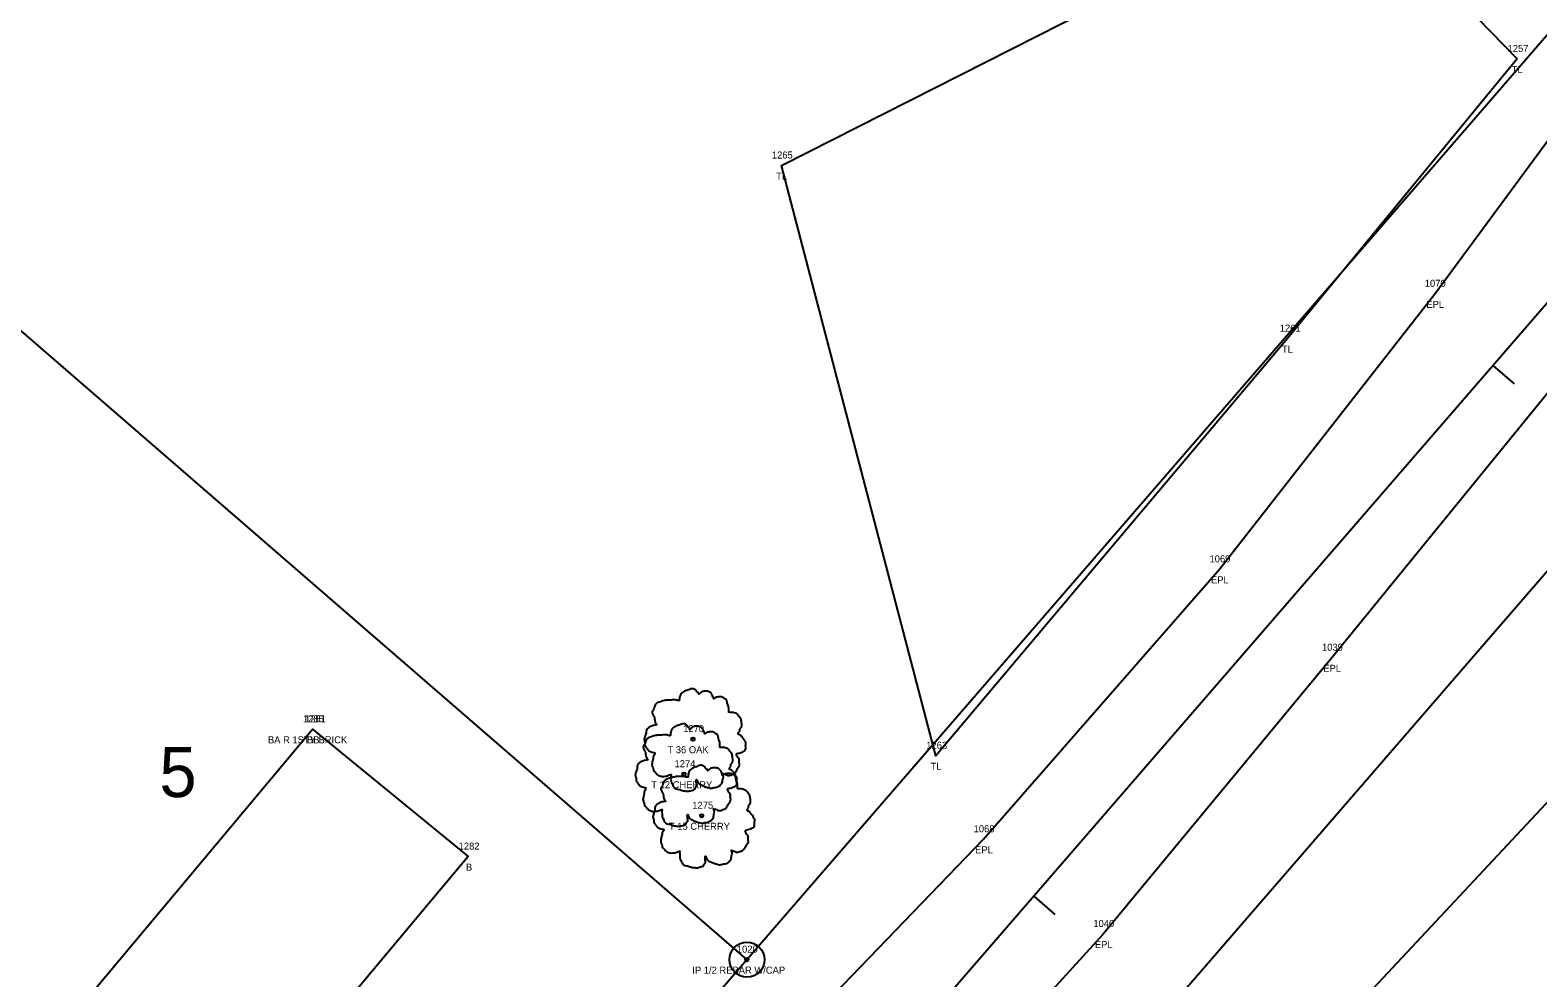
# Model space of a CAD drawing. Extents: x 1812113 to 1819860, y 1177290 to 1181185.
# Drawn here: x 1813774.2 to 1813989, y 1178275.6 to 1178410.7 of the extents above; entities that cross this region are included whole.
import ezdxf

# ---------------------------------------------------------------- set-up
doc = ezdxf.new("R2010")
doc.units = 0
for name, color, linetype in [('RD_EX_Bldg', 7, 'Continuous'), ('RD_EX_Bldg_txCode', 7, 'Continuous'), ('RD_EX_DV_Prop', 7, 'Continuous'), ('RD_EX_DV_Prop_txCode', 7, 'Continuous'), ('RD_EX_DV_PropPin', 7, 'Continuous'), ('RD_EX_DV_TX_Prop', 7, 'Continuous'), ('RD_EX_Fence_Other', 7, 'Continuous'), ('RD_EX_Road', 7, 'Continuous'), ('RD_EX_Road_txCode', 7, 'Continuous'), ('RD_EX_VEG', 7, 'Continuous'), ('RD_EX_VEG_txCode', 7, 'Continuous'), ('RD_HC_CL', 7, 'Continuous'), ('RD_HC_Data_Tic', 7, 'Continuous'), ('RD_SMD_Locator', 7, 'Continuous')]:
    doc.layers.add(name, color=color, linetype=linetype)

msp = doc.modelspace()

# ---------------------------------------------------------------- linework, layer by layer
at = {"layer": 'RD_EX_Bldg'}
msp.add_lwpolyline([(1813814.41, 1178311.05), (1813836.59, 1178292.91), (1813805.22, 1178255.39), (1813783.05, 1178273.53), (1813814.41, 1178311.05)], dxfattribs=at)
at = {"layer": 'RD_EX_DV_Prop'}
for p, q in [((1813876.31, 1178278.23), (1814007.16, 1178429.49)), ((1813914.12, 1178245.52), (1814044.97, 1178396.77)), ((1813876.31, 1178278.23), (1813762.97, 1178376.42)), ((1813820.68, 1178213.93), (1813876.31, 1178278.23))]:
    msp.add_line(p, q, dxfattribs=at)
at = {"layer": 'RD_EX_DV_PropPin'}
for radius in [2.5, 0.25]:
    msp.add_circle((1813876.31, 1178278.23), radius, dxfattribs=at)
at = {"layer": 'RD_EX_Fence_Other'}
msp.add_lwpolyline([(1814039.17, 1178321.6), (1814032.91, 1178334.96), (1814018.04, 1178330.3), (1813949.86, 1178257.34), (1813966.14, 1178241)], dxfattribs=at)
at = {"layer": 'RD_EX_Road'}
for p, q in [((1813974.31, 1178373.09), (1814001.91, 1178410.56)), ((1813943.63, 1178333.84), (1813974.31, 1178373.09)), ((1813991.69, 1178360.57), (1813959.64, 1178321.24)), ((1813910.02, 1178295.38), (1813943.63, 1178333.84)), ((1813959.64, 1178321.24), (1813927.09, 1178281.88)), ((1813874.69, 1178258.74), (1813910.02, 1178295.38)), ((1813927.09, 1178281.88), (1813899.48, 1178251.69))]:
    msp.add_line(p, q, dxfattribs=at)
at = {"layer": 'RD_EX_VEG'}
msp.add_lwpolyline([(1813961.33, 1178431.97), (1813986.04, 1178406.55), (1813953.31, 1178366.71), (1813903.24, 1178307.28), (1813881.24, 1178391.37), (1813961.33, 1178431.97)], dxfattribs=at)
for centre, radius in [((1813868.62, 1178309.64), 0.25), ((1813868.61, 1178309.62), 0.0001), ((1813867.35, 1178304.65), 0.25), ((1813867.34, 1178304.63), 0.0001), ((1813869.87, 1178298.73), 0.25), ((1813869.86, 1178298.71), 0.0001)]:
    msp.add_circle(centre, radius, dxfattribs=at)
for points in [[(1813868.75, 1178316.81), (1813868.45, 1178316.83), (1813868.13, 1178316.73), (1813867.88, 1178316.63), (1813867.65, 1178316.56), (1813867.43, 1178316.46), (1813867.13, 1178316.28), (1813866.9, 1178316.08), (1813866.78, 1178315.83), (1813866.73, 1178315.61), (1813866.68, 1178315.33), (1813866.68, 1178315.16), (1813866.55, 1178315.13), (1813866.4, 1178315.16), (1813866.15, 1178315.23), (1813865.9, 1178315.23), (1813865.65, 1178315.23), (1813865.3, 1178315.21), (1813864.95, 1178315.21), (1813864.68, 1178315.16), (1813864.35, 1178315.11), (1813863.98, 1178314.98), (1813863.63, 1178314.86), (1813863.33, 1178314.61), (1813863.08, 1178314.13), (1813862.96, 1178313.78), (1813862.81, 1178313.53), (1813862.96, 1178313.08), (1813863.13, 1178312.73), (1813863.15, 1178312.53), (1813863.23, 1178312.11), (1813863.33, 1178311.88), (1813863.45, 1178311.68), (1813863.38, 1178311.66), (1813863.01, 1178311.61), (1813862.71, 1178311.51), (1813862.28, 1178311.28), (1813862.06, 1178311.06), (1813861.96, 1178310.73), (1813861.93, 1178310.38), (1813861.83, 1178310.18), (1813861.76, 1178309.91), (1813861.73, 1178309.83), (1813861.68, 1178309.51), (1813861.78, 1178309.06), (1813861.81, 1178308.71), (1813861.93, 1178308.49), (1813862.08, 1178308.31), (1813862.26, 1178308.06), (1813862.66, 1178307.84), (1813862.98, 1178307.74), (1813863.18, 1178307.71), (1813863.01, 1178307.21), (1813862.96, 1178306.86), (1813862.83, 1178306.46), (1813862.83, 1178306.39), (1813862.78, 1178305.91), (1813862.93, 1178305.59), (1813863.01, 1178305.21), (1813863.18, 1178304.99), (1813863.45, 1178304.69), (1813863.78, 1178304.46), (1813864.28, 1178304.34), (1813864.68, 1178304.36), (1813865.25, 1178304.54), (1813865.5, 1178304.61), (1813865.48, 1178304.44), (1813865.5, 1178304.06), (1813865.5, 1178303.64), (1813865.65, 1178303.31), (1813865.75, 1178303.04), (1813865.9, 1178302.79), (1813866.23, 1178302.56), (1813866.63, 1178302.49), (1813867.05, 1178302.34), (1813867.5, 1178302.26), (1813868, 1178302.24), (1813868.6, 1178302.39), (1813868.88, 1178302.51), (1813868.98, 1178302.69), (1813869.18, 1178303.06), (1813869.13, 1178303.29), (1813869.15, 1178303.89), (1813869.25, 1178303.71), (1813869.43, 1178303.36), (1813869.93, 1178303.06), (1813870.33, 1178302.89), (1813870.8, 1178302.74), (1813871.1, 1178302.66), (1813871.58, 1178302.74), (1813871.95, 1178302.81), (1813872.33, 1178302.94), (1813872.63, 1178303.21), (1813872.8, 1178303.49), (1813872.85, 1178303.76), (1813872.93, 1178304.14), (1813872.98, 1178304.31)], [(1813872.98, 1178304.31), (1813872.9, 1178304.49), (1813872.85, 1178304.74), (1813872.93, 1178304.71), (1813873.1, 1178304.66), (1813873.38, 1178304.54), (1813873.6, 1178304.46), (1813873.93, 1178304.49), (1813874.2, 1178304.59), (1813874.65, 1178304.86), (1813874.92, 1178305.34), (1813875.2, 1178305.74), (1813875.27, 1178306.06), (1813875.22, 1178306.29), (1813875.2, 1178306.79), (1813875, 1178307.04), (1813874.95, 1178307.16), (1813874.85, 1178307.56), (1813874.92, 1178307.61), (1813875.2, 1178307.66), (1813875.57, 1178307.79), (1813875.85, 1178307.91), (1813876.07, 1178308.09), (1813876.15, 1178308.31), (1813876.12, 1178308.71), (1813876.17, 1178309.11), (1813876.1, 1178309.26), (1813876, 1178309.41), (1813875.92, 1178309.61), (1813875.77, 1178309.76), (1813875.67, 1178309.91), (1813875.57, 1178310.01), (1813875.45, 1178310.16), (1813875.27, 1178310.28), (1813875.12, 1178310.33), (1813875.07, 1178310.48), (1813875.22, 1178310.68), (1813875.27, 1178310.78), (1813875.3, 1178311.01), (1813875.52, 1178311.36), (1813875.57, 1178311.76), (1813875.52, 1178312.18), (1813875.47, 1178312.46), (1813875.32, 1178312.73), (1813875.12, 1178312.98), (1813875, 1178313.16), (1813874.82, 1178313.28), (1813874.5, 1178313.41), (1813874.25, 1178313.46), (1813873.9, 1178313.46), (1813873.7, 1178313.51), (1813873.73, 1178313.56), (1813873.73, 1178313.71), (1813873.73, 1178313.98), (1813873.65, 1178314.43), (1813873.5, 1178314.93), (1813873.5, 1178314.96), (1813873.4, 1178315.21), (1813873.18, 1178315.41), (1813873, 1178315.51), (1813872.8, 1178315.63), (1813872.55, 1178315.66), (1813872.25, 1178315.66), (1813871.98, 1178315.61), (1813871.78, 1178315.51), (1813871.6, 1178315.38), (1813871.53, 1178315.53), (1813871.43, 1178315.83), (1813871.38, 1178315.98), (1813871.23, 1178316.16), (1813871, 1178316.36), (1813870.55, 1178316.48), (1813869.93, 1178316.41), (1813869.63, 1178316.21), (1813869.48, 1178316.03), (1813869.43, 1178316.16), (1813869.23, 1178316.36), (1813869.13, 1178316.53), (1813868.95, 1178316.66), (1813868.8, 1178316.76), (1813868.7, 1178316.81)], [(1813867.48, 1178311.82), (1813867.18, 1178311.84), (1813866.86, 1178311.74), (1813866.61, 1178311.64), (1813866.38, 1178311.57), (1813866.16, 1178311.47), (1813865.86, 1178311.29), (1813865.63, 1178311.09), (1813865.51, 1178310.84), (1813865.46, 1178310.62), (1813865.41, 1178310.34), (1813865.41, 1178310.17), (1813865.28, 1178310.14), (1813865.13, 1178310.17), (1813864.88, 1178310.24), (1813864.63, 1178310.24), (1813864.38, 1178310.24), (1813864.03, 1178310.22), (1813863.68, 1178310.22), (1813863.41, 1178310.17), (1813863.08, 1178310.12), (1813862.71, 1178309.99), (1813862.36, 1178309.87), (1813862.06, 1178309.62), (1813861.81, 1178309.14), (1813861.68, 1178308.79), (1813861.53, 1178308.54), (1813861.68, 1178308.09), (1813861.86, 1178307.74), (1813861.88, 1178307.54), (1813861.96, 1178307.12), (1813862.06, 1178306.89), (1813862.18, 1178306.69), (1813862.11, 1178306.67), (1813861.73, 1178306.62), (1813861.43, 1178306.52), (1813861.01, 1178306.29), (1813860.78, 1178306.07), (1813860.68, 1178305.74), (1813860.66, 1178305.39), (1813860.56, 1178305.19), (1813860.48, 1178304.92), (1813860.46, 1178304.84), (1813860.41, 1178304.52), (1813860.51, 1178304.07), (1813860.53, 1178303.72), (1813860.66, 1178303.5), (1813860.81, 1178303.32), (1813860.98, 1178303.07), (1813861.38, 1178302.85), (1813861.71, 1178302.75), (1813861.91, 1178302.72), (1813861.73, 1178302.22), (1813861.68, 1178301.87), (1813861.56, 1178301.47), (1813861.56, 1178301.4), (1813861.51, 1178300.92), (1813861.66, 1178300.6), (1813861.73, 1178300.22), (1813861.91, 1178300), (1813862.18, 1178299.7), (1813862.51, 1178299.47), (1813863.01, 1178299.35), (1813863.41, 1178299.37), (1813863.98, 1178299.55), (1813864.23, 1178299.62), (1813864.21, 1178299.45), (1813864.23, 1178299.07), (1813864.23, 1178298.65), (1813864.38, 1178298.32), (1813864.48, 1178298.05), (1813864.63, 1178297.8), (1813864.96, 1178297.57), (1813865.36, 1178297.5), (1813865.78, 1178297.35), (1813866.23, 1178297.27), (1813866.73, 1178297.25), (1813867.33, 1178297.4), (1813867.61, 1178297.52), (1813867.71, 1178297.7), (1813867.91, 1178298.07), (1813867.86, 1178298.3), (1813867.88, 1178298.9), (1813867.98, 1178298.72), (1813868.15, 1178298.37), (1813868.65, 1178298.07), (1813869.05, 1178297.9), (1813869.53, 1178297.75), (1813869.83, 1178297.67), (1813870.3, 1178297.75), (1813870.68, 1178297.82), (1813871.05, 1178297.95), (1813871.35, 1178298.22), (1813871.53, 1178298.5), (1813871.58, 1178298.77), (1813871.65, 1178299.15), (1813871.7, 1178299.32)], [(1813871.7, 1178299.32), (1813871.63, 1178299.5), (1813871.58, 1178299.75), (1813871.65, 1178299.72), (1813871.83, 1178299.67), (1813872.1, 1178299.55), (1813872.33, 1178299.47), (1813872.65, 1178299.5), (1813872.93, 1178299.6), (1813873.38, 1178299.87), (1813873.65, 1178300.35), (1813873.93, 1178300.75), (1813874, 1178301.07), (1813873.95, 1178301.3), (1813873.93, 1178301.8), (1813873.73, 1178302.05), (1813873.68, 1178302.17), (1813873.58, 1178302.57), (1813873.65, 1178302.62), (1813873.93, 1178302.67), (1813874.3, 1178302.8), (1813874.58, 1178302.92), (1813874.8, 1178303.1), (1813874.88, 1178303.32), (1813874.85, 1178303.72), (1813874.9, 1178304.12), (1813874.83, 1178304.27), (1813874.73, 1178304.42), (1813874.65, 1178304.62), (1813874.5, 1178304.77), (1813874.4, 1178304.92), (1813874.3, 1178305.02), (1813874.18, 1178305.17), (1813874, 1178305.29), (1813873.85, 1178305.34), (1813873.8, 1178305.49), (1813873.95, 1178305.69), (1813874, 1178305.79), (1813874.03, 1178306.02), (1813874.25, 1178306.37), (1813874.3, 1178306.77), (1813874.25, 1178307.19), (1813874.2, 1178307.47), (1813874.05, 1178307.74), (1813873.85, 1178307.99), (1813873.73, 1178308.17), (1813873.55, 1178308.29), (1813873.23, 1178308.42), (1813872.98, 1178308.47), (1813872.63, 1178308.47), (1813872.43, 1178308.52), (1813872.45, 1178308.57), (1813872.45, 1178308.72), (1813872.45, 1178308.99), (1813872.38, 1178309.44), (1813872.23, 1178309.94), (1813872.23, 1178309.97), (1813872.13, 1178310.22), (1813871.9, 1178310.42), (1813871.73, 1178310.52), (1813871.53, 1178310.64), (1813871.28, 1178310.67), (1813870.98, 1178310.67), (1813870.7, 1178310.62), (1813870.5, 1178310.52), (1813870.33, 1178310.39), (1813870.25, 1178310.54), (1813870.15, 1178310.84), (1813870.1, 1178310.99), (1813869.95, 1178311.17), (1813869.73, 1178311.37), (1813869.28, 1178311.49), (1813868.65, 1178311.42), (1813868.35, 1178311.22), (1813868.2, 1178311.04), (1813868.15, 1178311.17), (1813867.95, 1178311.37), (1813867.86, 1178311.54), (1813867.68, 1178311.67), (1813867.53, 1178311.77), (1813867.43, 1178311.82)], [(1813870.01, 1178305.89), (1813869.71, 1178305.92), (1813869.38, 1178305.82), (1813869.13, 1178305.72), (1813868.91, 1178305.64), (1813868.68, 1178305.54), (1813868.38, 1178305.37), (1813868.16, 1178305.17), (1813868.03, 1178304.92), (1813867.98, 1178304.69), (1813867.93, 1178304.42), (1813867.93, 1178304.25), (1813867.81, 1178304.22), (1813867.66, 1178304.25), (1813867.41, 1178304.32), (1813867.16, 1178304.32), (1813866.91, 1178304.32), (1813866.56, 1178304.3), (1813866.21, 1178304.3), (1813865.93, 1178304.25), (1813865.61, 1178304.2), (1813865.23, 1178304.07), (1813864.88, 1178303.95), (1813864.58, 1178303.7), (1813864.33, 1178303.22), (1813864.21, 1178302.87), (1813864.06, 1178302.62), (1813864.21, 1178302.17), (1813864.38, 1178301.82), (1813864.41, 1178301.62), (1813864.48, 1178301.2), (1813864.58, 1178300.97), (1813864.71, 1178300.77), (1813864.63, 1178300.75), (1813864.26, 1178300.7), (1813863.96, 1178300.6), (1813863.53, 1178300.37), (1813863.31, 1178300.15), (1813863.21, 1178299.82), (1813863.18, 1178299.47), (1813863.08, 1178299.27), (1813863.01, 1178299), (1813862.98, 1178298.92), (1813862.93, 1178298.6), (1813863.03, 1178298.15), (1813863.06, 1178297.8), (1813863.18, 1178297.57), (1813863.33, 1178297.4), (1813863.51, 1178297.15), (1813863.91, 1178296.92), (1813864.23, 1178296.82), (1813864.43, 1178296.8), (1813864.26, 1178296.3), (1813864.21, 1178295.95), (1813864.08, 1178295.55), (1813864.08, 1178295.47), (1813864.03, 1178295), (1813864.18, 1178294.67), (1813864.26, 1178294.3), (1813864.43, 1178294.07), (1813864.71, 1178293.77), (1813865.03, 1178293.55), (1813865.53, 1178293.42), (1813865.93, 1178293.45), (1813866.51, 1178293.62), (1813866.76, 1178293.7), (1813866.73, 1178293.52), (1813866.76, 1178293.15), (1813866.76, 1178292.73), (1813866.91, 1178292.4), (1813867.01, 1178292.13), (1813867.16, 1178291.88), (1813867.48, 1178291.65), (1813867.88, 1178291.58), (1813868.31, 1178291.43), (1813868.76, 1178291.35), (1813869.26, 1178291.33), (1813869.86, 1178291.48), (1813870.13, 1178291.6), (1813870.23, 1178291.78), (1813870.43, 1178292.15), (1813870.38, 1178292.38), (1813870.41, 1178292.98), (1813870.51, 1178292.8), (1813870.68, 1178292.45), (1813871.18, 1178292.15), (1813871.58, 1178291.98), (1813872.05, 1178291.83), (1813872.35, 1178291.75), (1813872.83, 1178291.83), (1813873.2, 1178291.9), (1813873.58, 1178292.03), (1813873.88, 1178292.3), (1813874.05, 1178292.58), (1813874.1, 1178292.85), (1813874.18, 1178293.22), (1813874.23, 1178293.4)], [(1813874.23, 1178293.4), (1813874.15, 1178293.57), (1813874.1, 1178293.82), (1813874.18, 1178293.8), (1813874.35, 1178293.75), (1813874.63, 1178293.62), (1813874.85, 1178293.55), (1813875.18, 1178293.57), (1813875.45, 1178293.67), (1813875.9, 1178293.95), (1813876.18, 1178294.42), (1813876.45, 1178294.82), (1813876.53, 1178295.15), (1813876.48, 1178295.37), (1813876.45, 1178295.87), (1813876.25, 1178296.12), (1813876.2, 1178296.25), (1813876.1, 1178296.65), (1813876.18, 1178296.7), (1813876.45, 1178296.75), (1813876.83, 1178296.87), (1813877.1, 1178297), (1813877.33, 1178297.17), (1813877.4, 1178297.4), (1813877.38, 1178297.8), (1813877.43, 1178298.2), (1813877.35, 1178298.35), (1813877.25, 1178298.5), (1813877.18, 1178298.7), (1813877.03, 1178298.85), (1813876.93, 1178299), (1813876.83, 1178299.1), (1813876.7, 1178299.25), (1813876.53, 1178299.37), (1813876.38, 1178299.42), (1813876.33, 1178299.57), (1813876.48, 1178299.77), (1813876.53, 1178299.87), (1813876.55, 1178300.1), (1813876.78, 1178300.45), (1813876.83, 1178300.85), (1813876.78, 1178301.27), (1813876.73, 1178301.55), (1813876.58, 1178301.82), (1813876.38, 1178302.07), (1813876.25, 1178302.25), (1813876.08, 1178302.37), (1813875.75, 1178302.5), (1813875.5, 1178302.55), (1813875.15, 1178302.55), (1813874.95, 1178302.6), (1813874.98, 1178302.65), (1813874.98, 1178302.8), (1813874.98, 1178303.07), (1813874.9, 1178303.52), (1813874.75, 1178304.02), (1813874.75, 1178304.05), (1813874.65, 1178304.3), (1813874.43, 1178304.5), (1813874.25, 1178304.59), (1813874.05, 1178304.72), (1813873.8, 1178304.74), (1813873.5, 1178304.74), (1813873.23, 1178304.69), (1813873.03, 1178304.59), (1813872.85, 1178304.47), (1813872.78, 1178304.62), (1813872.68, 1178304.92), (1813872.63, 1178305.07), (1813872.48, 1178305.24), (1813872.25, 1178305.44), (1813871.8, 1178305.57), (1813871.18, 1178305.49), (1813870.88, 1178305.29), (1813870.73, 1178305.12), (1813870.68, 1178305.24), (1813870.48, 1178305.44), (1813870.38, 1178305.62), (1813870.21, 1178305.74), (1813870.06, 1178305.84), (1813869.96, 1178305.89)]]:
    msp.add_spline(points, degree=3, dxfattribs=at)
at = {"layer": 'RD_HC_CL'}
msp.add_line((1814048.02, 1178438.51), (1813851.74, 1178211.63), dxfattribs=at)
at = {"layer": 'RD_HC_Data_Tic'}
for p, q in [((1813982.59, 1178362.88), (1813985.62, 1178360.27)), ((1813917.17, 1178287.25), (1813920.19, 1178284.64))]:
    msp.add_line(p, q, dxfattribs=at)
at = {"layer": 'RD_SMD_Locator'}
for centre in [(1813986.04, 1178406.55), (1813881.24, 1178391.37), (1813974.31, 1178373.09), (1813953.31, 1178366.71), (1813943.63, 1178333.84), (1813959.64, 1178321.24), (1813814.41, 1178311.05), (1813814.41, 1178311.05), (1813903.24, 1178307.28), (1813910.02, 1178295.38), (1813836.59, 1178292.91), (1813927.09, 1178281.88)]:
    msp.add_circle(centre, 0.001, dxfattribs=at)

# ---------------------------------------------------------------- texts
at = {"layer": 'RD_EX_Bldg_txCode'}
for s, p in [('1285', (1813813.07, 1178312.05)), ('1281', (1813813.35, 1178312.05)), ('BA R 1STY BRICK', (1813808.07, 1178309.05)), ('BB', (1813813.63, 1178309.05)), ('1282', (1813835.24, 1178293.91)), ('B', (1813836.28, 1178290.91))]:
    msp.add_text(s, height=1, dxfattribs=at).set_placement(p)
at = {"layer": 'RD_EX_DV_Prop_txCode'}
for s, p in [('1020', (1813874.88, 1178279.23)), ('IP 1/2 REBAR W/CAP', (1813868.53, 1178276.23))]:
    msp.add_text(s, height=1, dxfattribs=at).set_placement(p)
at = {"layer": 'RD_EX_DV_TX_Prop'}
msp.add_text('5', height=7.14, dxfattribs=at).set_placement((1813792.6, 1178301.39))
at = {"layer": 'RD_EX_Road_txCode'}
for s, p in [('1070', (1813972.89, 1178374.09)), ('EPL', (1813973.11, 1178371.09)), ('1069', (1813942.22, 1178334.84)), ('EPL', (1813942.43, 1178331.84)), ('1039', (1813958.25, 1178322.24)), ('EPL', (1813958.43, 1178319.24)), ('1068', (1813908.61, 1178296.38)), ('EPL', (1813908.82, 1178293.38)), ('1040', (1813925.67, 1178282.88)), ('EPL', (1813925.89, 1178279.88))]:
    msp.add_text(s, height=1, dxfattribs=at).set_placement(p)
at = {"layer": 'RD_EX_VEG_txCode'}
for s, p in [('1257', (1813984.69, 1178407.55)), ('TL', (1813985.27, 1178404.55)), ('1265', (1813879.87, 1178392.37)), ('TL', (1813880.47, 1178389.37)), ('1261', (1813952.23, 1178367.71)), ('TL', (1813952.54, 1178364.71)), ('1270', (1813867.23, 1178310.64)), ('T 36 OAK', (1813864.99, 1178307.64)), ('1263', (1813901.87, 1178308.28)), ('1274', (1813866, 1178305.65)), ('TL', (1813902.47, 1178305.28)), ('T 12 CHERRY', (1813862.68, 1178302.65)), ('1275', (1813868.53, 1178299.73)), ('T 15 CHERRY', (1813865.2, 1178296.73))]:
    msp.add_text(s, height=1, dxfattribs=at).set_placement(p)

doc.saveas('drawing.dxf')
